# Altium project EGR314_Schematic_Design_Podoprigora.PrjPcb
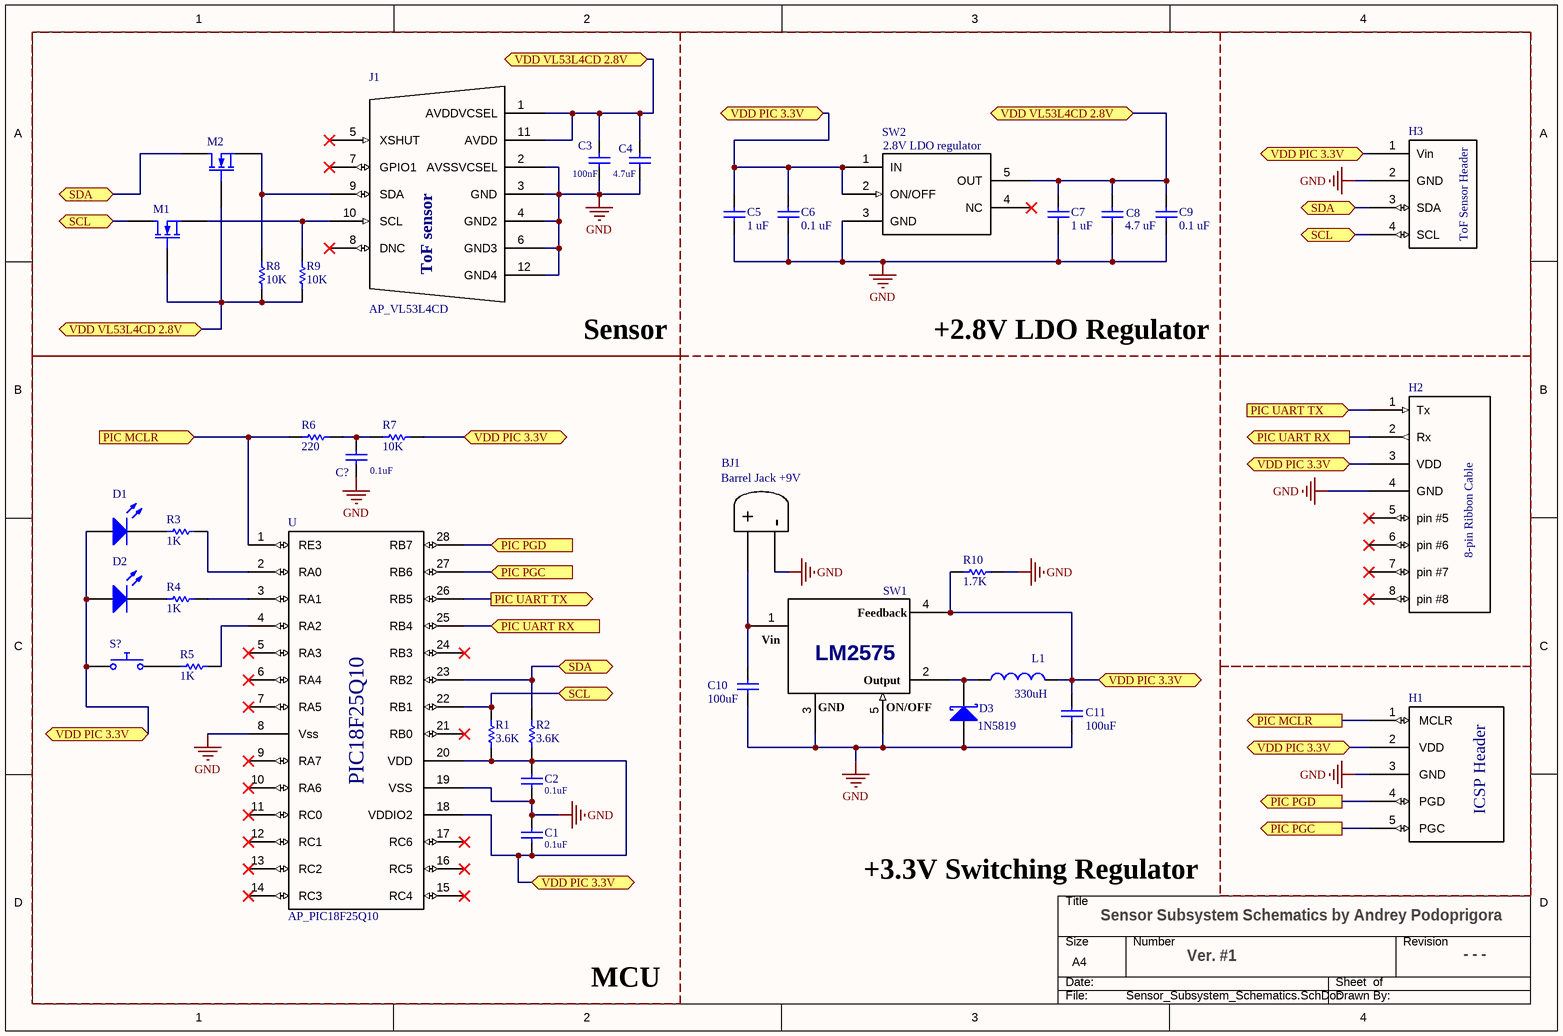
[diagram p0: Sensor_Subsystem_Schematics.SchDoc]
1 sheet, 37 parts. Net scope: flat (ports and power ports of the same name join across sheets).

## Sheet Sensor_Subsystem_Schematics.SchDoc: Sensor Subsystem Schematics by Andrey Podoprigora
size A4; SheetNumber: 1; SheetTotal: 1

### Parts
BJ1  AP_Barrel_Jack_9v  (value not drawn)
C1  value 0.1uF  (hidden comment: Capacitor)
C2  value 0.1uF  (hidden comment: Capacitor)
C3  value 100nF  (hidden comment: Capacitor)
C4  value 4.7uF  (hidden comment: Capacitor)
C5  value 1 uF
C6  value 0.1 uF
C7  value 1 uF
C8  value 4.7 uF
C9  value 0.1 uF
C10  value 100uF  (hidden comment: Capacitor)
C11  value 100uF  (hidden comment: Capacitor)
C?  value 0.1uF  (hidden comment: Capacitor)
D1  Light-Emitting Diode  (value not drawn)
D2  Light-Emitting Diode  (value not drawn)
D3  1N5819
H1  AP_ICSP_Header  (value not drawn)
H2  AP_8_pin_Ribbon_Cable  (value not drawn)
H3  AP_ToF_Header  (value not drawn)
J1  AP_VL53L4CD
L1  value 330uH  (hidden comment: Inductor)
M1  N-channel Power MOSFET VDMOS Model  (value not drawn)
M2  N-channel Power MOSFET VDMOS Model  (value not drawn)
R1  value 3.6K  (hidden comment: Resistor)
R2  value 3.6K  (hidden comment: Resistor)
R3  value 1K  (hidden comment: Resistor)
R4  value 1K  (hidden comment: Resistor)
R5  value 1K  (hidden comment: Resistor)
R6  value 220  (hidden comment: Resistor)
R7  value 10K  (hidden comment: Resistor)
R8  value 10K  (hidden comment: Resistor)
R9  value 10K  (hidden comment: Resistor)
R10  value 1.7K  (hidden comment: Resistor)
S?  Push Button Normally Opened  (value not drawn)
SW1  AP_LM2575  (value not drawn)
SW2  AP_LDO_2_8_V  (value not drawn)
U  AP_PIC18F25Q10

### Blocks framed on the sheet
Sensor: C3 C4 J1 M1 M2 R8 R9
+2.8V LDO Regulator: C5-C9 SW2
MCU: C1 C2 C? D1 D2 R1-R7 S? U

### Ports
PIC MCLR (in, see Sensor_Subsystem_Schematics[1B]), PIC MCLR (out, see Sensor_Subsystem_Schematics[4C]), PIC PGC (in, see Sensor_Subsystem_Schematics[1A]), PIC PGC (out, see Sensor_Subsystem_Schematics[3B]), PIC PGD (in, see Sensor_Subsystem_Schematics[1A]), PIC PGD (out, see Sensor_Subsystem_Schematics[3B]), PIC UART RX (in, see Sensor_Subsystem_Schematics[1C]), PIC UART RX (out, see Sensor_Subsystem_Schematics[3B]), PIC UART TX (in, see Sensor_Subsystem_Schematics[3B]), PIC UART TX (out, see Sensor_Subsystem_Schematics[1C]), SCL (bidir, see Sensor_Subsystem_Schematics[1D], Sensor_Subsystem_Schematics[3B]), SCL (bidir, see Sensor_Subsystem_Schematics[1D], Sensor_Subsystem_Schematics[4D]), SCL (bidir, see Sensor_Subsystem_Schematics[3B], Sensor_Subsystem_Schematics[4D]), SDA (bidir, see Sensor_Subsystem_Schematics[1D], Sensor_Subsystem_Schematics[3B]), SDA (bidir, see Sensor_Subsystem_Schematics[1D], Sensor_Subsystem_Schematics[4D]), SDA (bidir, see Sensor_Subsystem_Schematics[3B], Sensor_Subsystem_Schematics[4D]), VDD PIC 3.3V (bidir, see Sensor_Subsystem_Schematics[1B], Sensor_Subsystem_Schematics[1C], Sensor_Subsystem_Schematics[1D], Sensor_Subsystem_Schematics[2B], Sensor_Subsystem_Schematics[3A], Sensor_Subsystem_Schematics[3C], Sensor_Subsystem_Schematics[3D]), VDD PIC 3.3V (bidir, see Sensor_Subsystem_Schematics[1B], Sensor_Subsystem_Schematics[1C], Sensor_Subsystem_Schematics[1D], Sensor_Subsystem_Schematics[2B], Sensor_Subsystem_Schematics[3A], Sensor_Subsystem_Schematics[3C], Sensor_Subsystem_Schematics[4B]), VDD PIC 3.3V (bidir, see Sensor_Subsystem_Schematics[1B], Sensor_Subsystem_Schematics[1C], Sensor_Subsystem_Schematics[1D], Sensor_Subsystem_Schematics[2B], Sensor_Subsystem_Schematics[3A], Sensor_Subsystem_Schematics[3D], Sensor_Subsystem_Schematics[4B]), VDD PIC 3.3V (bidir, see Sensor_Subsystem_Schematics[1B], Sensor_Subsystem_Schematics[1C], Sensor_Subsystem_Schematics[1D], Sensor_Subsystem_Schematics[2B], Sensor_Subsystem_Schematics[3C], Sensor_Subsystem_Schematics[3D], Sensor_Subsystem_Schematics[4B]), VDD PIC 3.3V (bidir, see Sensor_Subsystem_Schematics[1B], Sensor_Subsystem_Schematics[1C], Sensor_Subsystem_Schematics[1D], Sensor_Subsystem_Schematics[3A], Sensor_Subsystem_Schematics[3C], Sensor_Subsystem_Schematics[3D], Sensor_Subsystem_Schematics[4B]), VDD PIC 3.3V (bidir, see Sensor_Subsystem_Schematics[1B], Sensor_Subsystem_Schematics[1C], Sensor_Subsystem_Schematics[2B], Sensor_Subsystem_Schematics[3A], Sensor_Subsystem_Schematics[3C], Sensor_Subsystem_Schematics[3D], Sensor_Subsystem_Schematics[4B]), VDD PIC 3.3V (bidir, see Sensor_Subsystem_Schematics[1B], Sensor_Subsystem_Schematics[1D], Sensor_Subsystem_Schematics[2B], Sensor_Subsystem_Schematics[3A], Sensor_Subsystem_Schematics[3C], Sensor_Subsystem_Schematics[3D], Sensor_Subsystem_Schematics[4B]), VDD PIC 3.3V (bidir, see Sensor_Subsystem_Schematics[1C], Sensor_Subsystem_Schematics[1D], Sensor_Subsystem_Schematics[2B], Sensor_Subsystem_Schematics[3A], Sensor_Subsystem_Schematics[3C], Sensor_Subsystem_Schematics[3D], Sensor_Subsystem_Schematics[4B]), VDD VL53L4CD 2.8V (bidir, see Sensor_Subsystem_Schematics[2D], Sensor_Subsystem_Schematics[3D]), VDD VL53L4CD 2.8V (bidir, see Sensor_Subsystem_Schematics[2D], Sensor_Subsystem_Schematics[4C]), VDD VL53L4CD 2.8V (bidir, see Sensor_Subsystem_Schematics[3D], Sensor_Subsystem_Schematics[4C])

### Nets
GND: BJ1.1(-) C1.2 C2.1 C3.1 C4.1 C5.1 C6.1 C7.1 C8.1 C9.1 C10.1 C11.1 C?.1 D3.1(A) H1.3(GND) H2.4(GND) H3.2(GND) J1.2(AVSSVCSEL) J1.3(GND) J1.4(GND2) J1.6(GND3) J1.12(GND4) R10.2 SW1.3(GND) SW1.5(ON/OFF) SW2.3(GND) U.8(Vss) U.19(VSS)
NetBJ1_1: BJ1.1(+) C10.2 SW1.1(Vin)
NetC1_1: C1.1 C2.2 C5.2 C6.2 C11.2 D1.1(A) D2.1(A) H1.2(VDD) H2.3(VDD) H3.1(Vin) L1.2 R1.1 R2.1 R7.2 R10.1 S?.1 SW1.4(Feedback) SW2.1(IN) SW2.2(ON/OFF) U.18(VDDIO2) U.20(VDD) ; port VDD PIC 3.3V
NetC3_2: C3.2 C4.2 C7.2 C8.2 C9.2 J1.1(AVDDVCSEL) J1.11(AVDD) M1.2(G) M2.2(G) R8.1 R9.1 SW2.5(OUT) ; port VDD VL53L4CD 2.8V
NetC?_2: C?.2 R6.2 R7.1
NetD1_2: D1.2(K) R3.1
NetD2_2: D2.2(K) R4.1
NetD3_2: D3.2(K) L1.1 SW1.2(Output)
NetH1_1: H1.1(MCLR) R6.1 U.1(RE3) ; port PIC MCLR
NetH1_4: H1.4(PGD) U.28(RB7) ; port PIC PGD
NetH1_5: H1.5(PGC) U.27(RB6) ; port PIC PGC
NetH2_1: H2.1(Tx) U.26(RB5) ; port PIC UART TX
NetH2_2: H2.2(Rx) U.25(RB4) ; port PIC UART RX
NetH3_3: H3.3(SDA) M2.1(D) R2.2 U.23(RB2) ; port SDA
NetH3_4: H3.4(SCL) M1.1(D) R1.2 U.22(RB1) ; port SCL
NetJ1_9: J1.9(SDA) M2.3(S) R8.2
NetJ1_10: J1.10(SCL) M1.3(S) R9.2
NetR3_2: R3.2 U.2(RA0)
NetR4_2: R4.2 U.3(RA1)
NetR5_1: R5.1 S?.2
NetR5_2: R5.2 U.4(RA2)

Not connected (* = marked no-connect by the designer): H2 5(pin_#5)* 6(pin_#6)* 7(pin_#7)* 8(pin_#8)*; J1 5(XSHUT)* 7(GPIO1)* 8(DNC)*; SW2 4(NC)*; U 5(RA3)* 6(RA4)* 7(RA5)* 9(RA7)* 10(RA6)* 11(RC0)* 12(RC1)* 13(RC2)* 14(RC3)* 15(RC4)* 16(RC5)* 17(RC6)* 21(RB0)* 24(RB3)*

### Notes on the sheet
- +3.3V Switching Regulator
- Ver. #1
- - - -

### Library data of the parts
C1-C11 C? = Capacitor: SimulationGenericComponent: True
D1 D2 = LED: AF: 1; BV: 0; BV_MAX: 1e99; EG: 1.11; FC: 0.5; IBV: 0.001; IS: 1e-14; MJSW: 0.33; NTUN: 30; TNOM: 27; XTI: 3; SimulationGenericComponent: True
D3 = Schottky Diode: AF: 1; BV: 0; BV_MAX: 1e99; EG: 1.11; FC: 0.5; IBV: 0.001; IS: 1e-14; MJSW: 0.33; NTUN: 30; TNOM: 27; XTI: 3; SimulationGenericComponent: True
H1 = AP_ICSP_Header: Header for the Microchip Snap
J1 = AP_VL53L4CD: Tof sensor type VL53L4CD
L1 = Inductor: SimulationGenericComponent: True
M1 M2 = MOSFET N-ch VDMOS: XTI: 0; A: 1; BV: 1e30; EG: 1.11; FC: 0.5; IBV: 1e-10; IS: 1e-14; PHI: 0.6; TNOM: 27; VJ: 0.8; SimulationGenericComponent: True
R1-R10 = Resistor: TC1: 0; SimulationGenericComponent: True
S? = Push Button NO: closed: 0; Rclosed: 1m; Ropen: 1Meg; SimulationGenericComponent: True
U = AP_PIC18F25Q10: PIC18F25Q10 represented as a library element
